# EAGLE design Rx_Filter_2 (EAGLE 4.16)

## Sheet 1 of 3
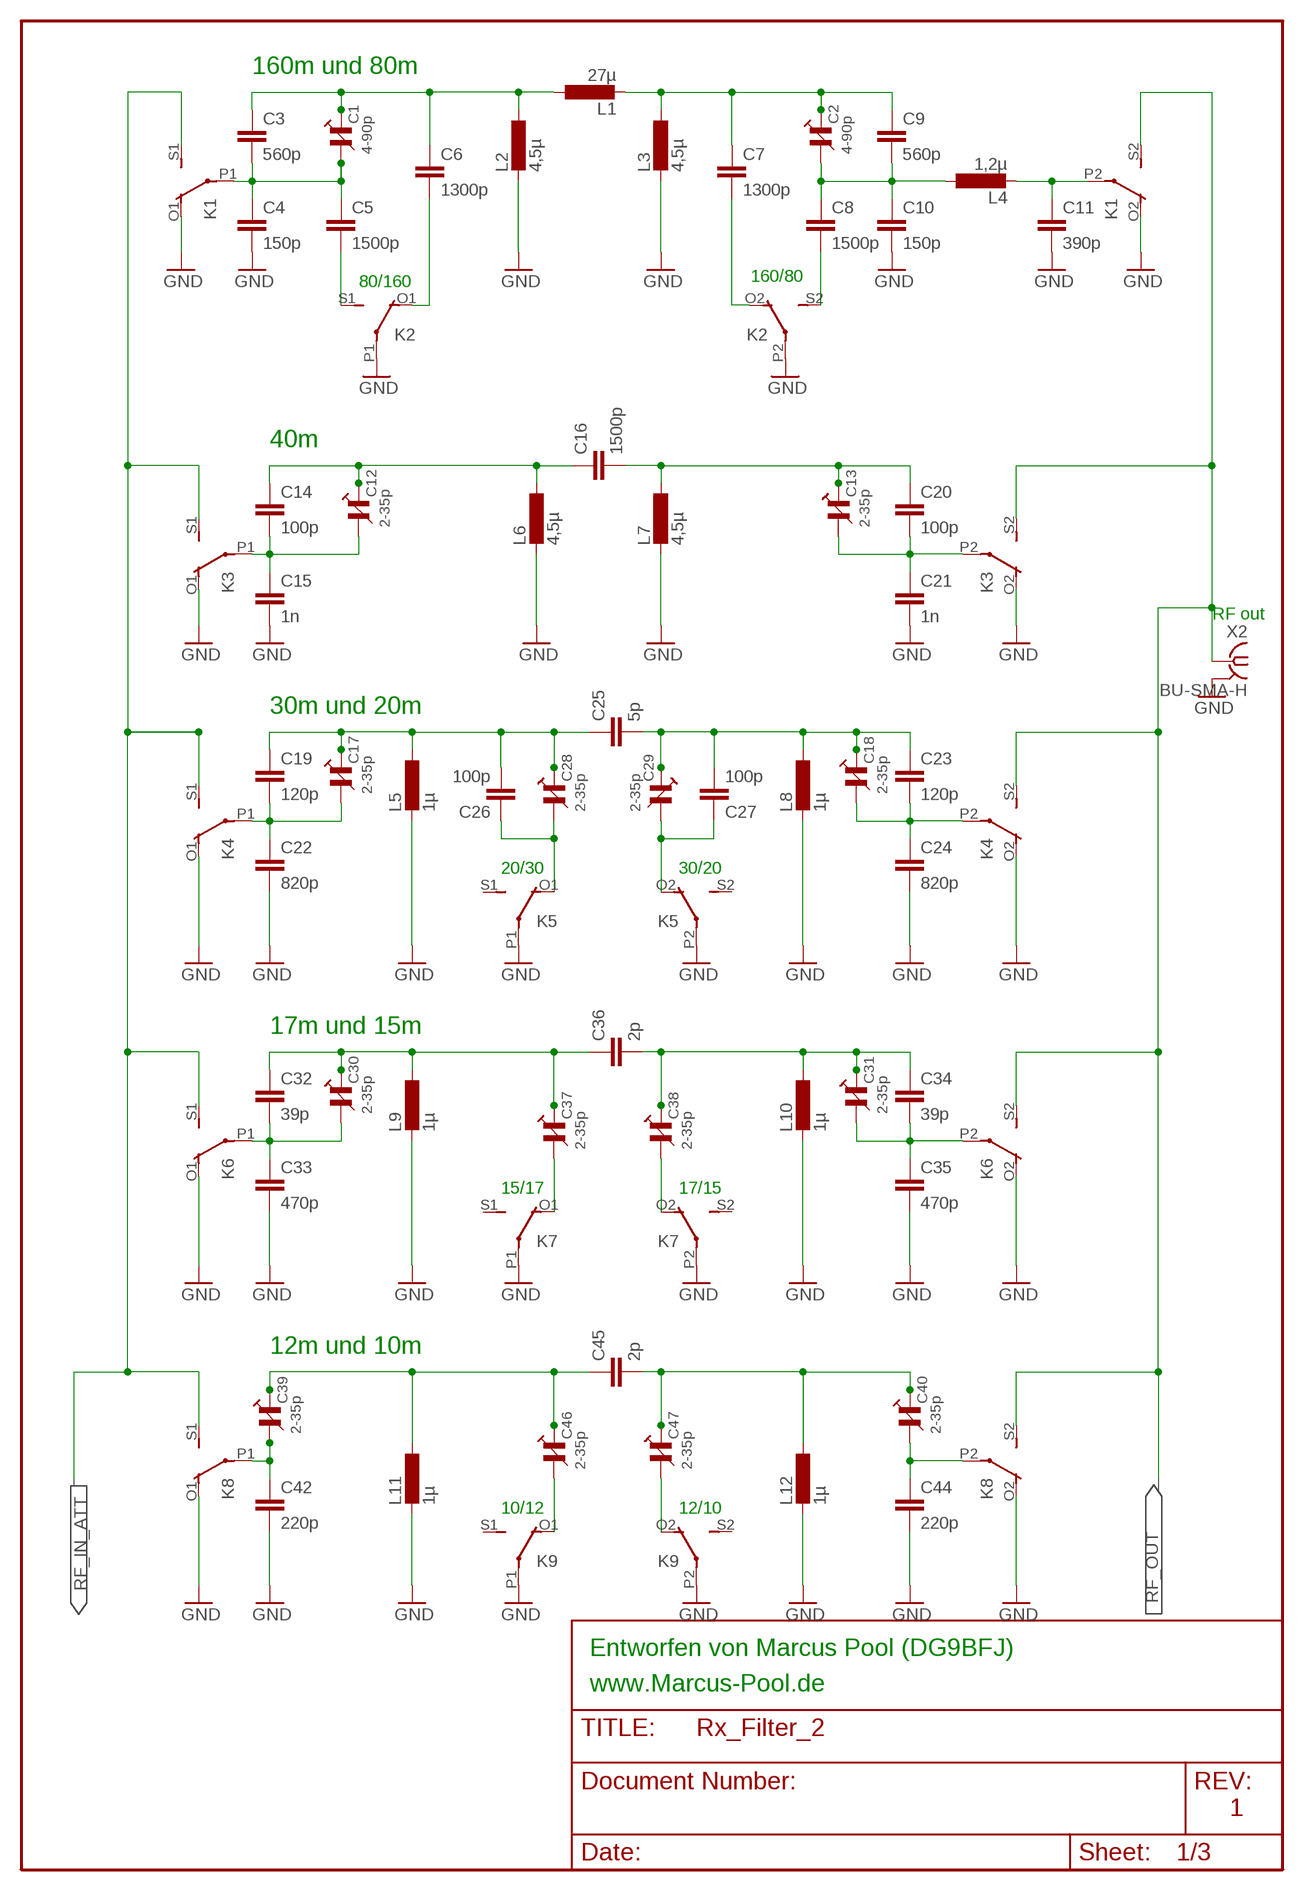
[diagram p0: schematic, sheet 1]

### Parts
C1  4-90p  808/3  [808/3]
C2  4-90p  808/3  [808/3]
C3  560p  C-EU050-050X075  [C050-050X075]
C4  150p  C-EU050-050X075  [C050-050X075]
C5  1500p  C-EU050-050X075  [C050-050X075]
C6  1300p  C-EU050-050X075  [C050-050X075]
C7  1300p  C-EU050-050X075  [C050-050X075]
C8  1500p  C-EU050-050X075  [C050-050X075]
C9  560p  C-EU050-050X075  [C050-050X075]
C10  150p  C-EU050-050X075  [C050-050X075]
C11  390p  C-EU050-050X075  [C050-050X075]
C12  2-35p  808/3  [808/3]
C13  2-35p  808/3  [808/3]
C14  100p  C-EU050-050X075  [C050-050X075]
C15  1n  C-EU050-050X075  [C050-050X075]
C16  1500p  C-EU050-050X075  [C050-050X075]
C17  2-35p  808/3  [808/3]
C18  2-35p  808/3  [808/3]
C19  120p  C-EU050-050X075  [C050-050X075]
C20  100p  C-EU050-050X075  [C050-050X075]
C21  1n  C-EU050-050X075  [C050-050X075]
C22  820p  C-EU050-050X075  [C050-050X075]
C23  120p  C-EU050-050X075  [C050-050X075]
C24  820p  C-EU050-050X075  [C050-050X075]
C25  5p  C-EU050-050X075  [C050-050X075]
C26  100p  C-EU050-050X075  [C050-050X075]
C27  100p  C-EU050-050X075  [C050-050X075]
C28  2-35p  808/3  [808/3]
C29  2-35p  808/3  [808/3]
C30  2-35p  808/3  [808/3]
C31  2-35p  808/3  [808/3]
C32  39p  C-EU050-050X075  [C050-050X075]
C33  470p  C-EU050-050X075  [C050-050X075]
C34  39p  C-EU050-050X075  [C050-050X075]
C35  470p  C-EU050-050X075  [C050-050X075]
C36  2p  C-EU050-050X075  [C050-050X075]
C37  2-35p  808/3  [808/3]
C38  2-35p  808/3  [808/3]
C39  2-35p  808/3  [808/3]
C40  2-35p  808/3  [808/3]
C42  220p  C-EU050-050X075  [C050-050X075]
C44  220p  C-EU050-050X075  [C050-050X075]
C45  2p  C-EU050-050X075  [C050-050X075]
C46  2-35p  808/3  [808/3]
C47  2-35p  808/3  [808/3]
K1  G6H2-100  [G6H2-100]
K2  G6H2-100  [G6H2-100]
K3  G6H2-100  [G6H2-100]
K4  G6H2-100  [G6H2-100]
K5  G6H2-100  [G6H2-100]
K6  G6H2-100  [G6H2-100]
K7  G6H2-100  [G6H2-100]
K8  G6H2-100  [G6H2-100]
K9  G6H2-100  [G6H2-100]
L1  27µ  L-EUTJ5-U1  [TJ5-U1]
L2  4,5µ  L-EUTJ3-U1  [TJ3-U1]
L3  4,5µ  L-EUTJ3-U1  [TJ3-U1]
L4  1,2µ  L-EUTJ3-U1  [TJ3-U1]
L5  1µ  L-EUTJ3-U1  [TJ3-U1]
L6  4,5µ  L-EUTJ3-U1  [TJ3-U1]
L7  4,5µ  L-EUTJ3-U1  [TJ3-U1]
L8  1µ  L-EUTJ3-U1  [TJ3-U1]
L9  1µ  L-EUTJ3-U1  [TJ3-U1]
L10  1µ  L-EUTJ3-U1  [TJ3-U1]
L11  1µ  L-EUTJ3-U1  [TJ3-U1]
L12  1µ  L-EUTJ3-U1  [TJ3-U1]
X2  BU-SMA-H  [BU-SMA-H]

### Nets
GND: C4.2 C10.2 C11.2 C15.2 C21.2 C22.2 C24.2 C33.2 C35.2 C42.2 C44.2 K1.O1(2:O) K1.O2(3:O) K2.P1(2:P) K2.P2(3:P) K3.O1(2:O) K3.O2(3:O) K4.O1(2:O) K4.O2(3:O) K5.P1(2:P) K5.P2(3:P) K6.O1(2:O) K6.O2(3:O) K7.P1(2:P) K7.P2(3:P) K8.O1(2:O) K8.O2(3:O) K9.P1(2:P) K9.P2(3:P) L2.2 L3.2 L5.2 L6.2 L7.2 L8.2 L9.2 L10.2 L11.2 L12.2 X2.2(GND) ; also sheet 2,3
N$1: C11.1 K1.P2(3:P) L4.2
N$2: C1.2 C3.2 C4.1 C5.1 K1.P1(2:P)
N$3: C1.1 C1.3 C3.1 C6.1 L1.1 L2.1
N$4: C2.1 C2.3 C7.1 C9.1 L1.2 L3.1
N$5: C2.2 C8.1 C9.2 C10.1 L4.1
N$6: C5.2 K2.S1(2:S)
N$7: C6.2 K2.O1(2:O)
N$8: C7.2 K2.O2(3:O)
N$9: C8.2 K2.S2(3:S)
N$12: C12.2 C14.2 C15.1 K3.P1(2:P)
N$13: C12.1 C12.3 C14.1 C16.1 L6.1
N$14: C13.1 C13.3 C16.2 C20.1 L7.1
N$15: C13.2 C20.2 C21.1 K3.P2(3:P)
N$16: C17.2 C19.2 C22.1 K4.P1(2:P)
N$17: C17.1 C17.3 C19.1 C25.1 C26.2 C28.1 C28.3 L5.1
N$18: C18.1 C18.3 C23.1 C25.2 C27.2 C29.1 C29.3 L8.1
N$19: C18.2 C23.2 C24.1 K4.P2(3:P)
N$20: C30.2 C32.2 C33.1 K6.P1(2:P)
N$21: C30.1 C30.3 C32.1 C36.1 C37.1 C37.3 L9.1
N$22: C26.1 C28.2 K5.O1(2:O)
N$23: C27.1 C29.2 K5.O2(3:O)
N$24: C31.1 C31.3 C34.1 C36.2 C38.1 C38.3 L10.1
N$25: C31.2 C34.2 C35.1 K6.P2(3:P)
N$26: C37.2 K7.O1(2:O)
N$27: C39.2 C42.1 K8.P1(2:P)
N$28: C39.1 C39.3 C45.1 C46.1 C46.3 L11.1
N$29: C40.1 C40.3 C45.2 C47.1 C47.3 L12.1
N$30: C38.2 K7.O2(3:O)
N$31: C40.2 C44.1 K8.P2(3:P)
N$32: C46.2 K9.O1(2:O)
N$33: C47.2 K9.O2(3:O)
RF_IN_ATT: K1.S1(2:S) K3.S1(2:S) K4.S1(2:S) K6.S1(2:S) K8.S1(2:S) ; also sheet 3
RF_OUT: K1.S2(3:S) K3.S2(3:S) K4.S2(3:S) K6.S2(3:S) K8.S2(3:S) X2.1 ; also sheet 3

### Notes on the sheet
- 160m und 80m
- 160/80
- 80/160
- 40m
- RF out
- 30m und 20m
- 20/30 | 30/20
- 17m und 15m
- 15/17 | 17/15
- 12m und 10m
- 10/12 | 12/10
- Entworfen von Marcus Pool (DG9BFJ)
- www.Marcus-Pool.de
- 1

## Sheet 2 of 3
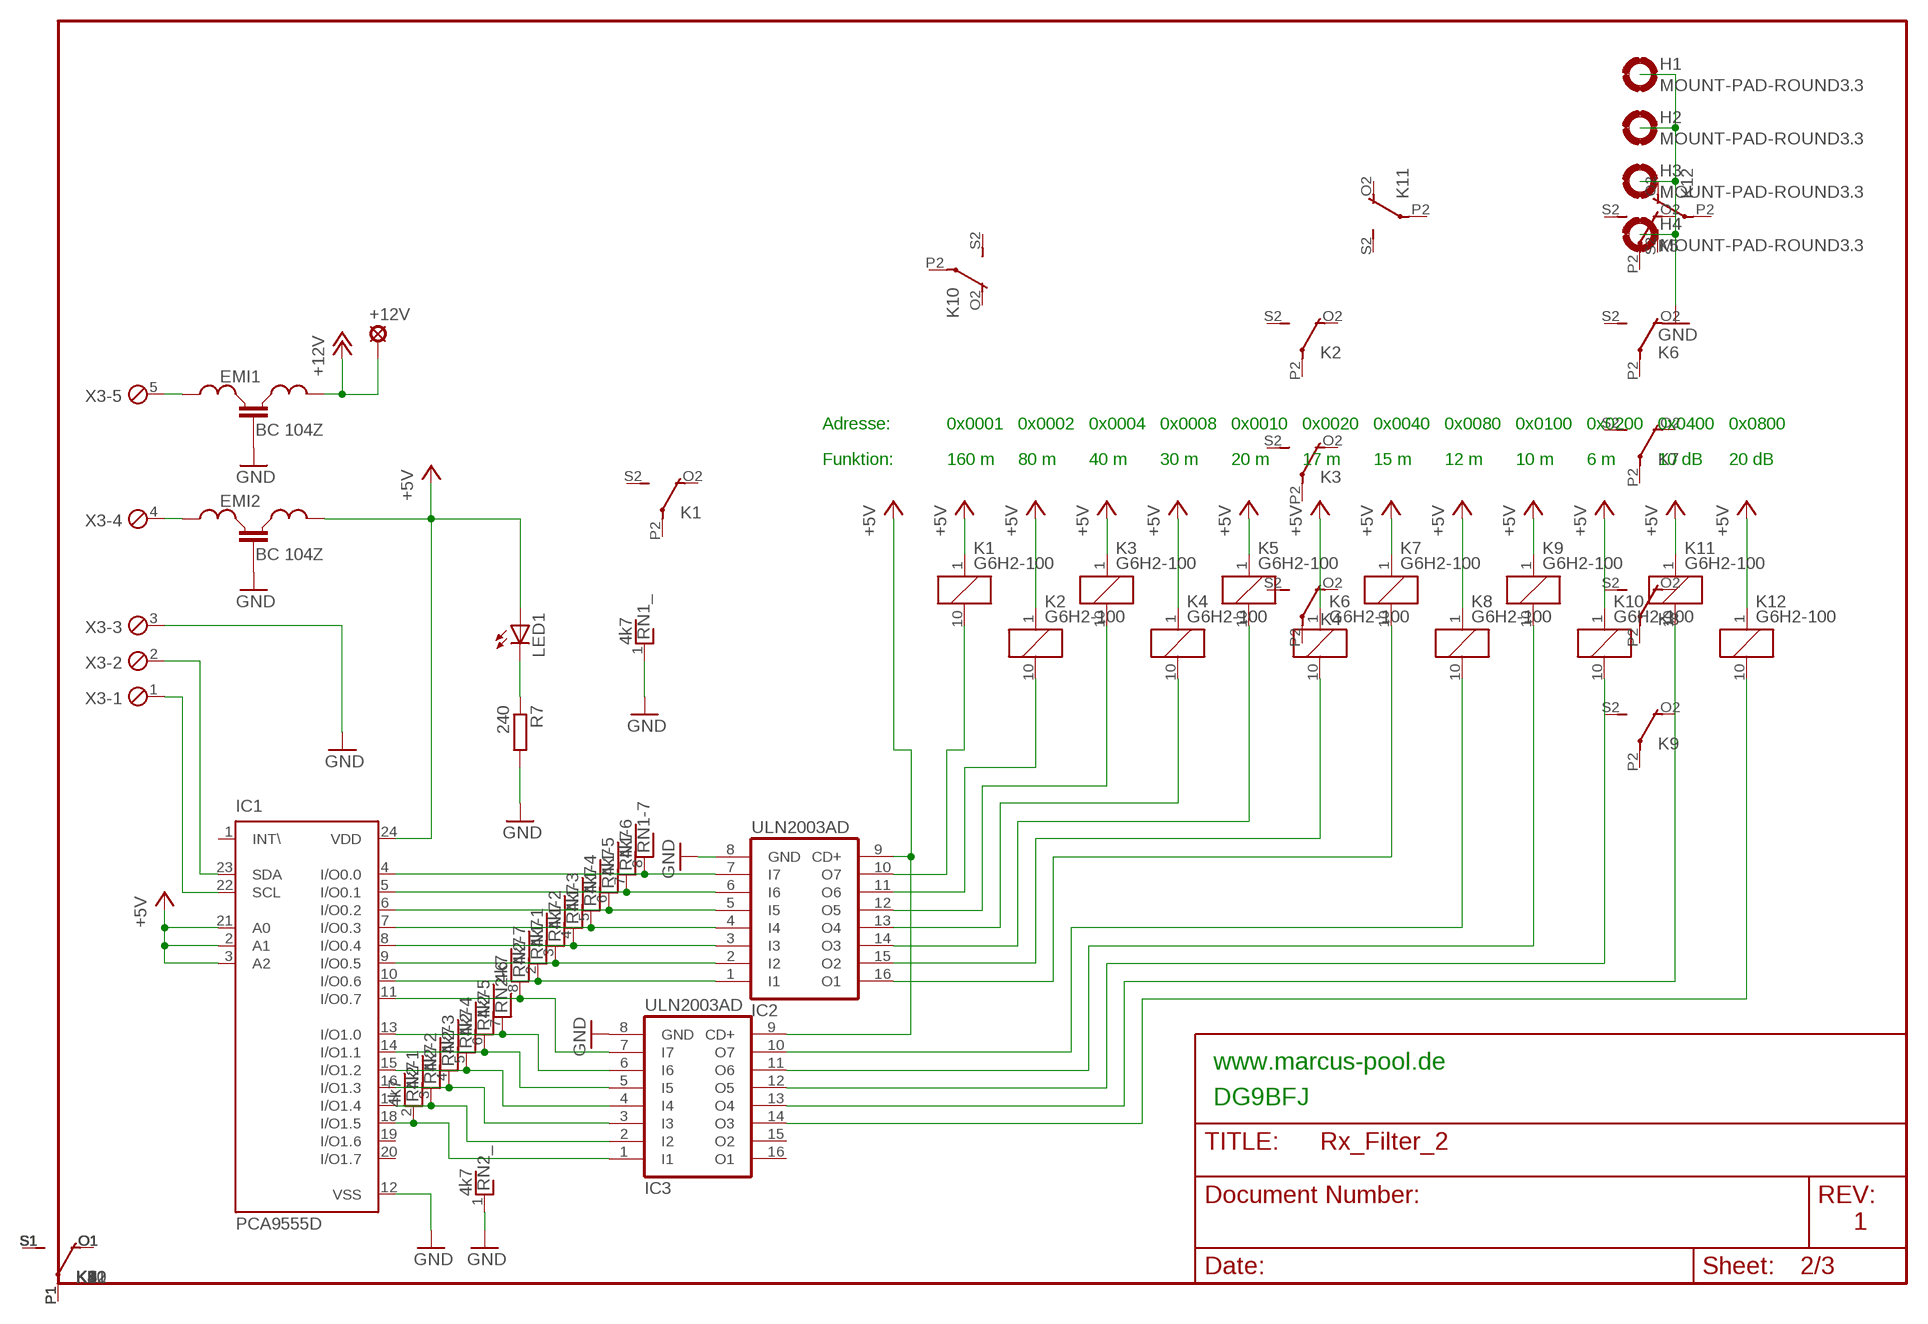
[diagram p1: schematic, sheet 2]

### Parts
+12V  LSP10  [LSP10]
EMI1  BC 104Z  DSS30655  [DSS30655]
EMI2  BC 104Z  DSS30655  [DSS30655]
H1  MOUNT-PAD-ROUND3.3  [3,3-PAD]
H2  MOUNT-PAD-ROUND3.3  [3,3-PAD]
H3  MOUNT-PAD-ROUND3.3  [3,3-PAD]
H4  MOUNT-PAD-ROUND3.3  [3,3-PAD]
IC1  PCA9555D  [SO24]
IC2  ULN2003AD  [SO16]
IC3  ULN2003AD  [SO16]
K10  G6H2-100  [G6H2-100]
K11  G6H2-100  [G6H2-100]
K12  G6H2-100  [G6H2-100]
LED1  LEDCHIP-LED0805  [CHIP-LED0805]
R7  240  R-EU_M0805  [M0805]
RN1  4k7  RNX7  [RN-8]
RN2  4k7  RNX7  [RN-8]
X3  MPT5  [5POL254]

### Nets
+5V: EMI2.3 IC1.2(A1) IC1.3(A2) IC1.21(A0) IC1.24(VDD) IC2.9(CD+) IC3.9(CD+) K1.1 K2.1 K3.1 K4.1 K5.1 K6.1 K7.1 K8.1 K9.1 K10.1 K11.1 K12.1 LED1.A
+12V: +12V.MP EMI1.3
GND: EMI1.2 EMI2.2 H1.B3,3(MOUNT) H2.B3,3(MOUNT) H3.B3,3(MOUNT) H4.B3,3(MOUNT) IC1.12(VSS) IC2.8(GND) IC3.8(GND) R7.2 RN1.1 RN2.1 X3.3 ; also sheet 1,3
N$10: IC1.10(I/O0.6) IC2.1(I1) RN1.2
N$34: IC1.9(I/O0.5) IC2.2(I2) RN1.3
N$39: IC1.8(I/O0.4) IC2.3(I3) RN1.4
N$40: IC1.7(I/O0.3) IC2.4(I4) RN1.5
N$41: IC1.6(I/O0.2) IC2.5(I5) RN1.6
N$42: IC1.5(I/O0.1) IC2.6(I6) RN1.7
N$43: IC1.4(I/O0.0) IC2.7(I7) RN1.8
N$44: IC1.11(I/O0.7) IC3.7(I7) RN2.8
N$45: IC1.13(I/O1.0) IC3.6(I6) RN2.7
N$46: IC1.14(I/O1.1) IC3.5(I5) RN2.6
N$47: IC1.15(I/O1.2) IC3.4(I4) RN2.5
N$48: IC1.16(I/O1.3) IC3.3(I3) RN2.4
N$49: IC1.17(I/O1.4) IC3.2(I2) RN2.3
N$50: IC1.18(I/O1.5) IC3.1(I1) RN2.2
N$51: IC2.10(O7) K1.10
N$54: IC2.11(O6) K2.10
N$55: IC2.12(O5) K3.10
N$56: IC2.13(O4) K4.10
N$57: IC2.14(O3) K5.10
N$58: IC2.15(O2) K6.10
N$59: IC2.16(O1) K7.10
N$60: IC3.10(O7) K8.10
N$61: IC3.11(O6) K9.10
N$62: IC3.12(O5) K10.10
N$68: IC3.13(O4) K11.10
N$69: IC3.14(O3) K12.10
N$70: IC1.22(SCL) X3.1
N$71: IC1.23(SDA) X3.2
N$72: LED1.C R7.1
N$73: EMI1.1 X3.5
N$74: EMI2.1 X3.4
Unconnected: IC1.1(INT\) IC1.19(I/O1.6) IC1.20(I/O1.7) IC3.15(O2) IC3.16(O1) K5.S1(2:S) K5.S2(3:S) K7.S1(2:S) K7.S2(3:S) K9.S1(2:S) K9.S2(3:S)

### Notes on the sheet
- Adresse: | 0x0001 | 0x0002 | 0x0004 | 0x0008 | 0x0010 | 0x0020 | 0x0040 | 0x0080 | 0x0100 | 0x0200 | 0x0400 | 0x0800
- Funktion: | 160 m | 80 m | 40 m | 30 m | 20 m | 17 m | 15 m | 12 m | 10 m | 6 m | 10 dB | 20 dB
- www.marcus-pool.de
- DG9BFJ
- 1

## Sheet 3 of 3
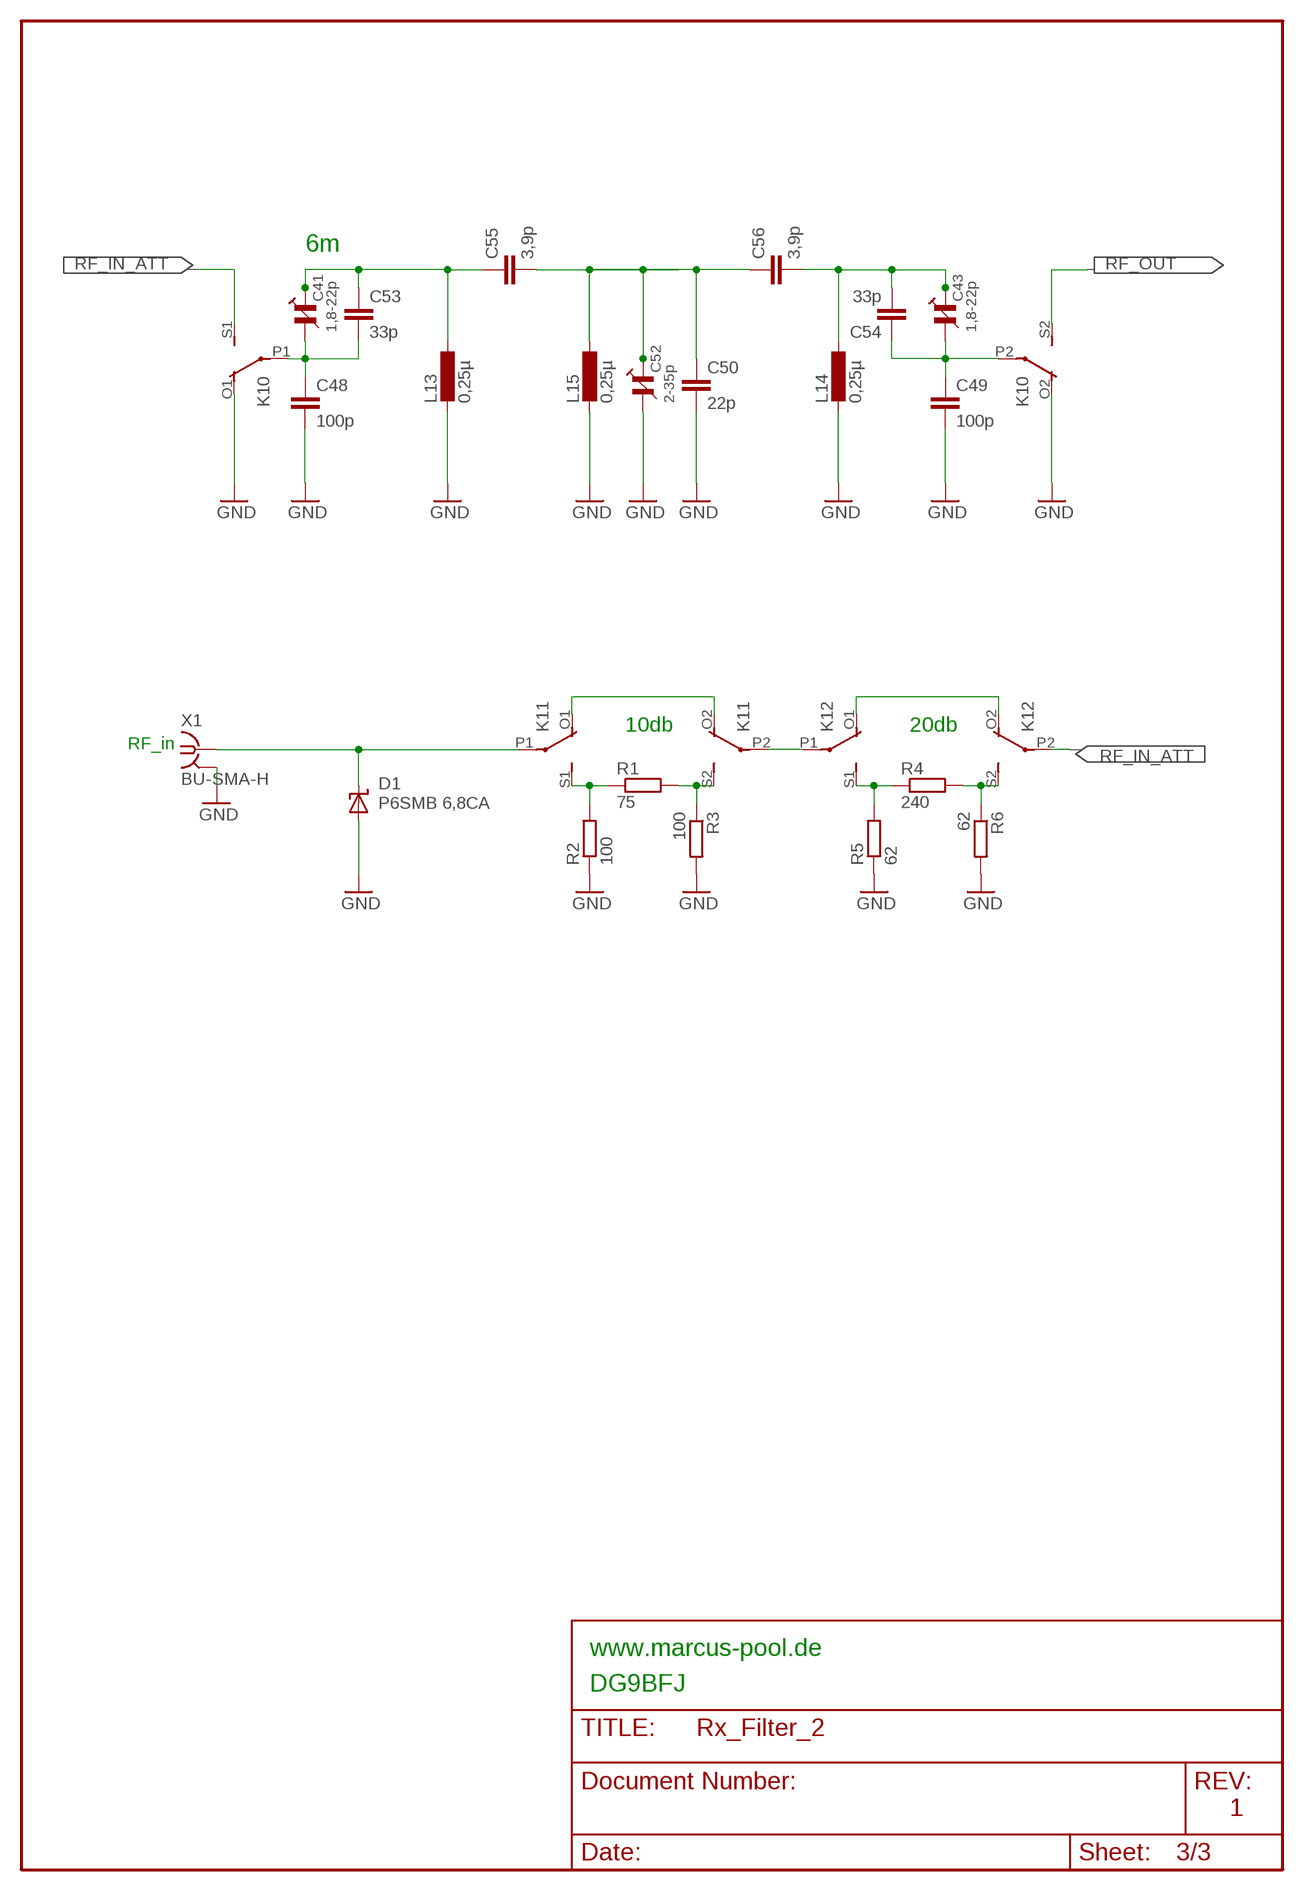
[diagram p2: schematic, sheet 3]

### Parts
C41  1,8-22p  808/3  [808/3]
C43  1,8-22p  808/3  [808/3]
C48  100p  C-EU050-050X075  [C050-050X075]
C49  100p  C-EU050-050X075  [C050-050X075]
C50  22p  C-EU050-050X075  [C050-050X075]
C52  2-35p  808/3  [808/3]
C53  33p  C-EU050-050X075  [C050-050X075]
C54  33p  C-EU050-050X075  [C050-050X075]
C55  3,9p  C-EU050-050X075  [C050-050X075]
C56  3,9p  C-EU050-050X075  [C050-050X075]
D1  P6SMB 6,8CA  SUPPRESSOR-SMBJ  [SMBJ]
L13  0,25µ  L-EUTJ3-U1  [TJ3-U1]
L14  0,25µ  L-EUTJ3-U1  [TJ3-U1]
L15  0,25µ  L-EUTJ3-U1  [TJ3-U1]
R1  75  R-EU_M0805  [M0805]
R2  100  R-EU_M0805  [M0805]
R3  100  R-EU_M0805  [M0805]
R4  240  R-EU_M0805  [M0805]
R5  62  R-EU_M0805  [M0805]
R6  62  R-EU_M0805  [M0805]
X1  BU-SMA-H  [BU-SMA-H]

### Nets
GND: C48.2 C49.2 C50.2 C52.2 D1.A K10.O1(2:O) K10.O2(3:O) L13.2 L14.2 L15.2 R2.1 R3.2 R5.1 R6.2 X1.2(GND) ; also sheet 1,2
N$11: C41.2 C48.1 C53.2 K10.P1(2:P)
N$35: C41.1 C41.3 C53.1 C55.1 L13.1
N$36: C43.1 C43.3 C54.2 C56.2 L14.1
N$37: C43.2 C49.1 C54.1 K10.P2(3:P)
N$38: C50.1 C52.1 C52.3 C55.2 C56.1 L15.1
N$52: K11.O1(2:O) K11.O2(3:O)
N$53: K11.S1(2:S) R1.1 R2.2
N$63: K11.S2(3:S) R1.2 R3.1
N$64: K11.P2(3:P) K12.P1(2:P)
N$65: K12.O1(2:O) K12.O2(3:O)
N$66: K12.S1(2:S) R4.1 R5.2
N$67: K12.S2(3:S) R4.2 R6.1
N$76: D1.C K11.P1(2:P) X1.1
RF_IN_ATT: K10.S1(2:S) K12.P2(3:P) ; also sheet 1
RF_OUT: K10.S2(3:S) ; also sheet 1

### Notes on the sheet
- 6m
- 10db | 20db
- RF_in
- www.marcus-pool.de
- DG9BFJ
- 1

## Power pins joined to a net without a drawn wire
GND: X1.3(GND) X1.4(GND) X1.5(GND) X2.3(GND) X2.4(GND) X2.5(GND)

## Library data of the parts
+12V = solpad:LSP10: SOLDER PAD
C1 C2 C12 C13 C17 C18 C28-C31 C37-C41 C43 C46 C47 C52 = Cap-Dreh:808/3
C3-C11 C14-C16 C19-C27 C32-C36 C42 C44 C45 C48-C50 C53-C56 = rcl:C-EU: CAPACITOR, European symbol
D1 = diode:SUPPRESSOR-: Suppressor diode
EMI1 EMI2 = ds(s)30655:DSS30655
H1-H4 = holes:MOUNT-PAD-ROUND: MOUNTING PAD, round
IC1 = micro-philips:PCA9555: 16-bit I2C and SMBus I/O port with interrupt Source: PCA9555_5.pdf
IC2 IC3 = uln-udn:ULN2003A: DRIVER ARRAY
K1-K12 = relay:G6H2-100: RELAY 2 x switch, 0.5 A/125 V AC, 1 A/30 V DC, Omron
L1-L15 = rcl:L-EU: INDUCTOR, European symbol
LED1 = led:LED: LED
R1-R7 = rcl:R-EU_: RESISTOR, European symbol
RN1 RN2 = resistor-net:RNX7: RESISTOR NETWORK
X1 X2 = RSC_IB_LIB:BU-SMA-H
X3 = con-phoenix-254:MPT5: PHOENIX CONNECTOR

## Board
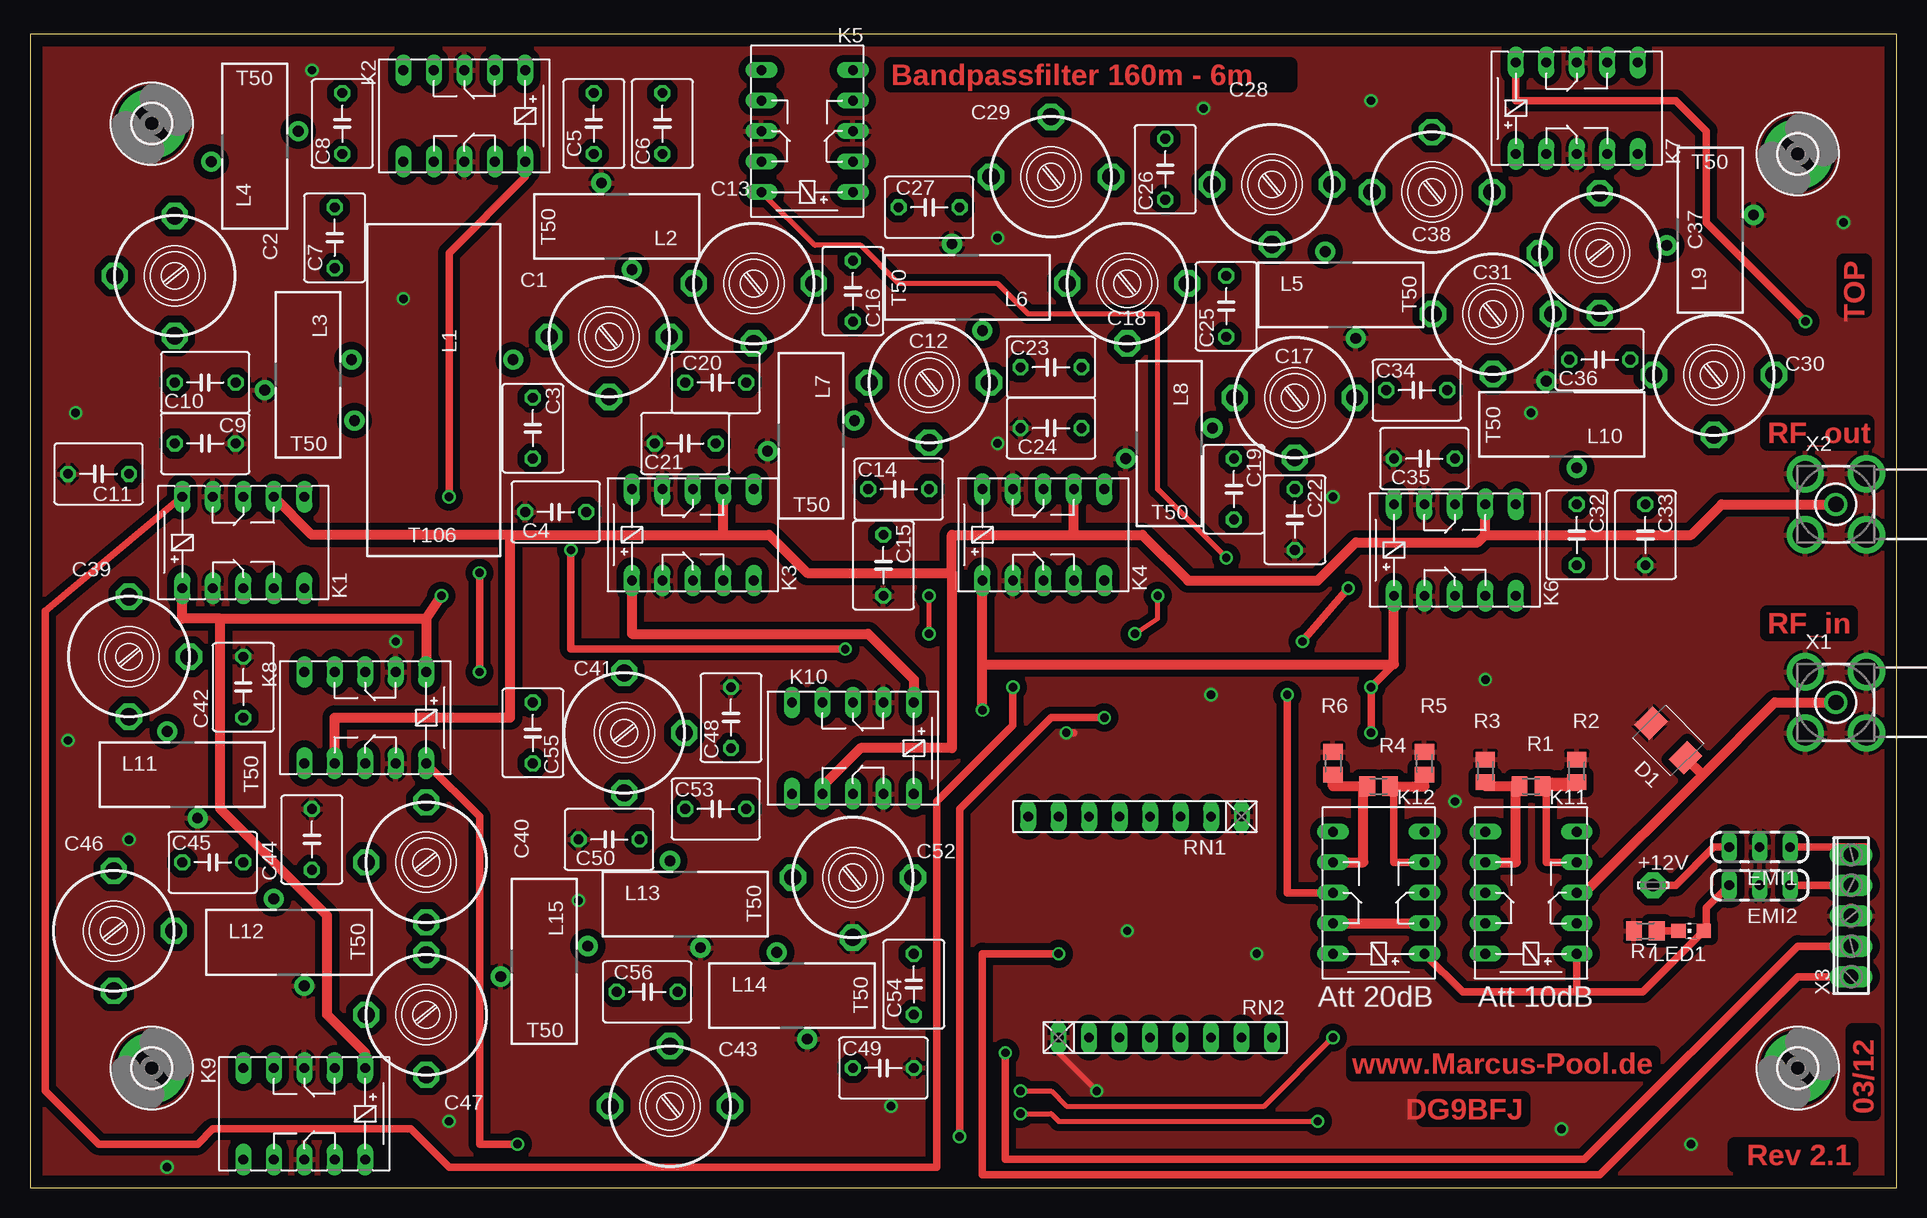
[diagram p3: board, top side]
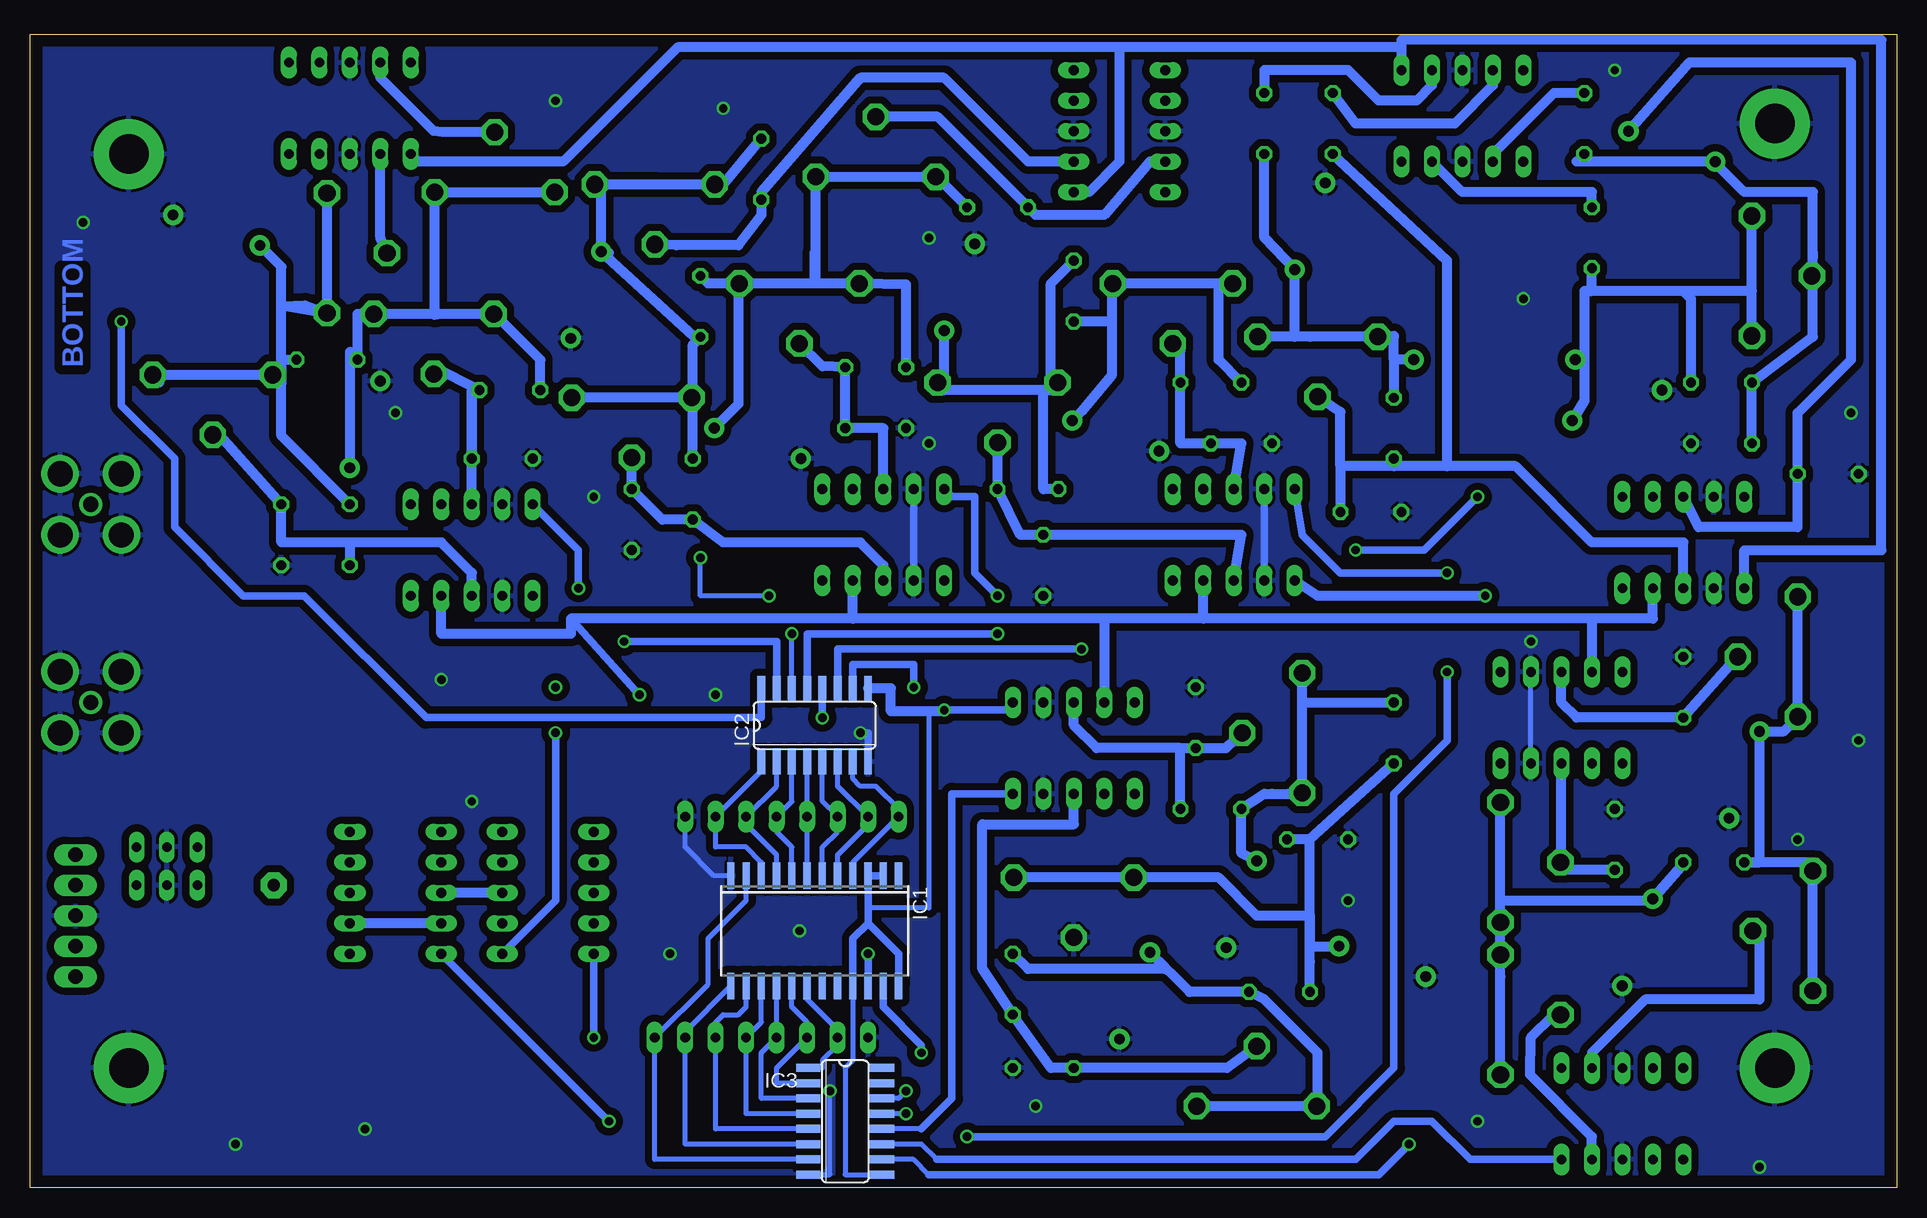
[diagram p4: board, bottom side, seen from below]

Size 155.56 x 96.19 mm. Coordinates in mm from the lower left corner, seen from the top.
Outline: 0,0 155.56,0 155.56,96.19 0,96.19 0,0
Copper layers (1*16): Top 0.035mm / dielectric 1.5mm / Bottom 0.035mm
Design rules "Bilex DRU": minimum track width 10mil, minimum drill 24mil, track to track 10mil, track to pad 10mil, pad to pad 10mil, via to via 10mil, smd to smd 10mil, copper to edge 40mil, drill to drill 8mil, minimum pad ring 10mil, minimum via ring 8mil, stop-mask expansion 4mil, vias tented up to drill 0mil, thermal gap 10mil

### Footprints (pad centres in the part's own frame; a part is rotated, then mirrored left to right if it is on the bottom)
LSP10 = drill 1.016 pad 2.159 octagon: MP 0,0
808/3 = drill 1.422 pad 2.184 octagon: 1 -5,0; 2 0,-5; 3 5,0
C050-050X075 = drill 0.813 octagon: 1 -2.54,0; 2 2.54,0
SMBJ = smd 1.78 x 2.16: A 2.04,0; C -2.03,0
DSS30655 = drill 0.8 long: 1 -2.54,0; 2 0,0; 3 2.54,0
3,3-PAD = drill 3.3 pad 5.842 round: B3,3 0,0
SO24 = smd 0.6 x 2.2: 1 -6.985,-4.6; 2 -5.715,-4.6; 3 -4.445,-4.6; 4 -3.175,-4.6; 5 -1.905,-4.6; 6 -0.635,-4.6; 7 0.635,-4.6; 8 1.905,-4.6; 9 3.175,-4.6; 10 4.445,-4.6; 11 5.715,-4.6; 12 6.985,-4.6; 13 6.985,4.6; 14 5.715,4.6; 15 4.445,4.6; 16 3.175,4.6; 17 1.905,4.6; 18 0.635,4.6; 19 -0.635,4.6; 20 -1.905,4.6; 21 -3.175,4.6; 22 -4.445,4.6; 23 -5.715,4.6; 24 -6.985,4.6
SO16 = smd 0.66 x 2.032: 1 -4.445,-3.073; 2 -3.175,-3.073; 3 -1.905,-3.073; 4 -0.635,-3.073; 5 0.635,-3.073; 6 1.905,-3.073; 7 3.175,-3.073; 8 4.445,-3.073; 9 4.445,3.073; 10 3.175,3.073; 11 1.905,3.073; 12 0.635,3.073; 13 -0.635,3.073; 14 -1.905,3.073; 15 -3.175,3.073; 16 -4.445,3.073
G6H2-100 = drill 0.813 long: 1 -5.08,-3.81; 5 5.08,-3.81; 6 5.08,3.81; 10 -5.08,3.81; O1 -2.54,-3.81; O2 -2.54,3.81; P1 0,-3.81; P2 0,3.81; S1 2.54,-3.81; S2 2.54,3.81
TJ5-U1 = drill 0.9 pad 1.676 round: 1 -6.605,-2.54; 2 6.605,2.54
TJ3-U1 = drill 0.9 pad 1.676 round: 1 -3.935,-1.27; 2 3.3,1.27
CHIP-LED0805 = smd 1.2 x 1.2: A 0,-1.05; C 0,1.05
M0805 = smd 1.3 x 1.6: 1 -0.95,0; 2 0.95,0
RN-8 = drill 0.813 long: 1 -8.89,0; 2 -6.35,0; 3 -3.81,0; 4 -1.27,0; 5 1.27,0; 6 3.81,0; 7 6.35,0; 8 8.89,0
BU-SMA-H = drill 1.27 round: 1 0,0 | drill 2.1 round: 2 -2.55,2.55; 3 2.55,2.55; 4 2.55,-2.55; 5 -2.55,-2.55
5POL254 = drill 1.2 long: 1 -5.08,0; 2 -2.54,0; 3 0,0; 4 2.54,0; 5 5.08,0

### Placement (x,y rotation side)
+12V  135.25,25.23 0 top
C1  48.25,70.95 0 top
C2  12.06,76.03 270 top
C3  41.9,63.34 270 top
C4  43.81,56.35 180 top
C5  46.98,88.73 90 top
C6  52.7,88.73 90 top
C7  25.39,79.21 90 top
C8  26.03,88.73 90 top
C9  14.6,67.14 180 top
C10  14.6,62.06 0 top
C11  5.71,59.52 180 top
C12  74.93,67.14 0 top
C13  60.32,75.4 0 top
C14  72.39,58.26 0 top
C15  71.12,51.91 270 top
C16  68.58,74.77 270 top
C17  105.41,65.88 0 top
C18  91.44,75.4 0 top
C19  100.33,58.26 270 top
C20  57.14,67.14 0 top
C21  54.6,62.06 180 top
C22  105.41,55.72 270 top
C23  85.09,68.41 0 top
C24  85.09,63.34 180 top
C25  99.69,73.49 90 top
C26  94.61,84.92 90 top
C27  74.93,81.75 0 top
C28  103.5,83.65 0 top
C29  85.09,84.29 180 top
C30  140.33,67.78 0 top
C31  121.92,72.86 0 top
C32  128.9,54.45 270 top
C33  134.62,54.45 270 top
C34  115.56,66.51 0 top
C35  116.2,60.8 180 top
C36  130.81,69.05 180 top
C37  130.81,77.94 270 top
C38  116.84,83.02 180 top
C39  8.25,44.29 90 top
C40  33.02,27.14 270 top
C41  49.52,37.94 90 top
C42  17.78,41.74 90 top
C43  53.34,6.82 180 top
C44  23.49,29.05 90 top
C45  15.23,27.14 0 top
C46  6.98,21.43 90 top
C47  33.02,14.44 270 top
C48  58.41,39.2 90 top
C49  71.12,10 0 top
C50  48.25,29.05 180 top
C52  68.58,25.87 0 top
C53  57.14,31.59 0 top
C54  73.66,16.98 90 top
C55  41.9,37.94 270 top
C56  51.43,16.35 0 top
D1  136.52,37.3 135 top
EMI1  144.14,28.41 180 top
EMI2  144.14,25.23 180 top
H1  147.31,10 0 top
H2  147.31,86.19 0 top
H3  10.15,10 0 top
H4  10.15,88.73 0 top
IC1  90.17,21.43 180 bottom
IC2  90.17,38.57 0 bottom
IC3  87.62,5.55 270 bottom
K1  17.78,53.81 0 top
K2  36.19,89.37 180 top
K3  55.24,54.45 0 top
K4  84.45,54.45 0 top
K5  64.77,88.1 90 top
K6  118.74,53.18 0 top
K7  128.9,90 0 top
K8  27.94,39.2 180 top
K9  22.86,6.18 180 top
K10  68.58,36.66 180 top
K11  125.09,24.6 90 top
K12  112.39,24.6 90 top
L1  33.65,66.51 180 top
L2  48.89,80.48 90 top
L3  22.86,67.78 180 top
L4  19.05,86.83 0 top
L5  109.22,74.13 270 top
L6  78.1,75.4 90 top
L7  64.77,62.7 180 top
L8  94.61,62.06 180 top
L9  140.33,79.84 0 top
L10  127.63,63.97 90 top
L11  12.69,34.12 270 top
L12  21.59,20.16 270 top
L13  54.6,23.33 270 top
L14  63.49,15.71 270 top
L15  42.54,18.89 180 top
LED1  138.43,21.43 90 top
R1  125.09,33.49 180 top
R2  128.9,34.76 270 top
R3  121.28,34.76 90 top
R4  112.39,33.49 180 top
R5  116.2,35.4 270 top
R6  108.58,35.4 90 top
R7  134.62,21.43 180 top
RN1  92.07,30.95 180 top
RN2  94.61,12.54 0 top
X1  150.49,40.48 0 top
X2  150.49,56.98 0 top
X3  151.76,22.7 90 top

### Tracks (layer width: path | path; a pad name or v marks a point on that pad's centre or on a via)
+5V  (via drill 0.7, 0.7 pad 1.02)
  Top 0.61: K12.1 119.38,16.35 128.9,16.35 | 128.9,16.35 K11.1 | v111.76,37.94 v111.76,41.74 113.66,43.65 | 128.9,16.35 134.4,16.35 LED1.A 139.69,21.43 139.69,23.33 EMI2.3
  Top 0.813: 33.02,47.46 K8.1 | 33.02,47.46 v34.28,49.37 | 15.87,47.46 33.02,47.46 | K3.1 50.16,46.19 69.84,46.19 73.66,42.38 K10.1 | 79.37,43.65 K4.1 | K6.1 113.66,43.65 79.37,43.65 | v79.37,39.84 79.37,43.65 | K9.1 27.94,11.27 24.76,14.44 24.76,22.7 15.87,31.59 15.87,47.46 | 15.87,47.46 12.69,47.46 K1.1
  Bottom 0.406: IC1.3 85.72,25.87 85.56,26.03 | IC3.9 87.62,1.1 87.62,10 86.99,10.63 86.99,16.98 IC1.21 | 83.81,39.74 80.64,39.74 80.64,23.33 85.72,23.33
  Bottom 0.61: K10.1 73.66,39.84 v79.37,39.84 | K12.1 111.76,23.96 v111.76,37.94 | 86.99,16.98 86.99,20.79 85.72,22.06 | 85.72,22.06 85.72,23.33 85.72,25.87 | IC1.24 83.18,19.52 85.72,22.06 | 85.56,26.03 IC1.2
  Bottom 0.813: 41.27,95.08 64.77,95.08 | 64.77,95.08 64.77,85.56 67.31,83.02 K5.1 | K7.1 123.19,85.56 111.12,85.56 101.59,95.08 64.77,95.08 | K3.1 48.25,49.37 v34.28,49.37 | v79.37,39.84 79.37,39.74 83.81,39.74 83.81,41.64 IC2.9 | 41.27,95.08 41.27,95.72 1.27,95.72 1.27,53.18 12.69,53.18 K1.1 | 41.27,95.08 K2.1
+12V
  Top 0.61: EMI1.3 140.33,28.41 137.16,25.23 +12V.MP
GND  (via drill 0.7, 0.7 pad 1.02)
  Top 0.406: v88.9,8.09 85.72,11.27 RN2.1
  Top 0.61: v86.36,37.94 86.99,37.94
  Bottom 0.406: IC1.12 98.58,26.03 100.96,28.41 RN1.1 | IC3.8 88.9,1.1 v88.9,8.09 | K8.O2 K8.O1
  Bottom 0.61: IC2.8 85.72,37.94 v86.36,37.94 | K3.O1 K3.O2 | K4.O1 K4.O2
  other vias: 118.74,32.22 97.79,90 111.76,90.64 151.12,80.48 121.28,42.38 125.09,64.6 80.64,79.21 80.64,62.06 31.11,74.13 3.17,37.3 8.25,29.05 34.92,5.55 45.71,23.96 71.75,6.82 30.48,45.55 127.63,4.92 138.43,3.65 102.23,19.52 23.49,93.18 3.81,64.6 91.44,21.43 108.58,57.62 98.42,41.11 11.42,1.74
  pour Top (isolate 0.61): 0.63,95.72 154.94,95.72 154.94,0.47 0.63,0.47
  pour Bottom (isolate 0.61): 0.63,95.72 154.94,95.72 154.94,0.47 0.63,0.47
N$1
  Bottom 0.813: K1.P2 16.51,55.08 8.25,55.08 C11.1 8.25,64.6 3.81,69.05 3.81,93.81 17.27,93.81 L4.2
N$2
  Bottom 0.813: C1.2 46.35,64.68 46.35,60.16 | 46.35,60.16 C4.1 | 41.9,60.16 46.35,60.16 | C5.1 37.46,77.3 37.46,60.16 | 37.46,60.16 31.75,60.16 25.39,53.81 17.78,53.81 K1.P1 | 37.46,60.16 41.9,60.16 | 41.9,60.16 C3.2
N$3
  Bottom 0.813: 41.9,69.05 C3.1 | 41.9,70.95 C1.1 | C1.1 48.89,70.95 | 48.89,70.95 50.16,70.95 L2.1 52.7,79.21 C6.1 | C1.1 41.9,71.03 41.9,70.95 | L1.1 41.9,69.05 | 41.9,69.05 41.9,70.95 | 48.89,70.95 C1.3
N$4
  Bottom 0.813: 26.67,69.05 L3.1 26.03,69.05 | 26.03,74.77 26.03,69.05 | 26.03,74.77 25.39,74.77 C7.1 | 26.03,69.05 26.03,65.62 L1.2 | 17.78,74.77 26.03,74.77 | 12.06,74.77 17.78,74.77 | 17.78,74.77 17.14,74.13 C9.1 | C2.3 12.06,74.77 | 12.06,74.77 C2.1
N$5
  Bottom 0.813: C10.1 C9.2 6.98,70.95 6.98,77.94 | 6.98,77.94 6.98,83.02 12.69,83.02 15.23,85.56 | 6.98,77.94 C2.2 | 15.23,85.56 L4.1 | 15.23,85.56 26.67,85.56 C8.1
N$6
  Bottom 0.813: K2.S1 33.65,91.91 36.82,88.73 45.08,88.73 C5.2
N$7
  Bottom 0.813: K2.O1 38.73,91.91 40,90.64 43.17,90.64 45.71,93.18 52.7,93.18 C6.2
N$8
  Bottom 0.813: K2.O2 36.19,83.02 25.39,83.02 C7.2
N$9
  Bottom 0.813: K2.S2 33.65,86.19 28.57,91.27 C8.2
N$10
  Bottom 0.406: IC2.1 94.61,34.76 RN1.2 98.42,28.41 95.88,28.41 94.61,27.14 IC1.10
N$11
  Bottom 0.813: K10.P1 68.58,38.57 66.67,36.66 59.68,36.66 | 59.68,36.66 C48.1 55.88,36.66 | 55.88,36.66 C41.2 | 59.68,36.66 55.88,36.66 | C53.2 59.68,36.66
N$12
  Bottom 0.813: K3.P1 54.6,54.45 C15.1 73.02,54.45 C14.2 C12.2
N$13
  Bottom 0.813: C14.1 71.12,58.26 71.12,66.51 | 71.12,66.51 C12.1 70.48,66.51 | 71.12,66.51 70.48,66.51 | 79.37,66.51 L6.1 | 70.48,66.51 70.48,75.4 C16.1 | 71.12,66.51 79.37,66.51 | 79.37,66.51 C12.3
N$14
  Bottom 0.813: L7.1 67.94,64.73 65.4,67.78 65.4,74.13 | 65.4,74.13 65.4,72.22 C16.2 | 65.4,74.13 65.4,75.4 C13.3 C13.1 | C13.1 55.24,75.4 | C13.1 55.24,75.32 56.51,75.4 56.51,69.05 C20.1
N$15
  Bottom 0.813: C13.2 59.68,69.77 C20.2 59.68,62.06 C21.1 54.6,62.06 K3.P2
N$16
  Bottom 0.813: C17.2 C22.1 102.87,55.72 C19.2 97.79,53.81 86.36,53.81 84.45,51.91 K4.P1
N$17
  Bottom 0.813: C19.1 100.33,65.79 C17.1 100.33,65.88 | 100.33,65.88 100.33,70.32 C25.1 100.2,70.95 L5.1 | L5.1 107.31,77.94 | 107.95,83.73 C28.1 | L5.1 107.95,83.73 | 107.95,83.73 107.39,83.65 C28.3 C28.1 | C28.1 97.79,83.65 C26.2 | 100.33,65.88 C17.3
N$18
  Bottom 0.813: C25.2 99.06,75.4 96.52,75.4 | C18.1 86.36,75.4 | C18.1 90.17,75.4 | C18.1 C18.3 | C18.3 96.52,75.4 | L8.1 96.52,65.36 96.52,75.4 | C18.1 82.55,75.32 C23.1 | 90.09,77.94 90.09,75.48 90.17,75.4 | 90.09,77.94 C29.1 C29.3 80.01,84.29 C27.2 | 90.09,77.94 90.17,77.94 90.17,75.4 | 90.17,75.4 C18.3
N$19
  Bottom 0.813: C18.2 89.53,68.49 C23.2 C24.1 84.45,63.34 K4.P2
N$20
  Bottom 0.813: K6.P1 118.74,51.27 121.28,53.81 128.9,53.81 | 128.9,53.81 134.62,53.81 C33.1 139.78,62.78 C30.2 | 128.9,53.81 C32.2
N$21
  Bottom 0.813: C30.1 134.62,68.41 | C30.1 134.62,67.06 134.62,62.7 C32.1 | C30.1 134.62,67.14 134.62,68.41 | 134.62,73.49 134.62,73.57 | L9.1 134.62,76.79 134.62,73.57 | 134.62,68.41 134.62,69.05 | 134.62,69.05 134.62,73.49 | 134.62,69.05 C36.1 | C37.3 132.63,73.57 134.62,73.49 | C37.3 C37.1 | 134.62,73.57 C37.3 | 144.78,67.14 C30.3 C30.1
N$22
  Bottom 0.813: C28.2 101.68,78.57 96.52,78.57 94.61,81.11 C26.1 94.61,83.02 86.36,92.54 79.37,92.54 72.39,85.56 K5.O1
N$23
  Bottom 0.813: C29.2 79.93,89.29 C27.1 71.75,81.11 66.04,81.11 62.22,85.56 K5.O2
N$24
  Bottom 0.813: 121.28,72.86 C31.3 128.27,72.86 C36.2 128.9,69.68 L10.1 | 116.84,72.86 C31.1 | C31.1 121.28,72.86 | 117.47,72.86 121.28,72.86 | C31.1 117.47,72.86 | 116.84,72.86 117.47,72.86 | 116.84,72.86 113.03,69.05 C34.1 | 111.76,83.02 C38.3 C38.1 121.84,72.78 121.28,72.86
N$25
  Bottom 0.813: 118.74,66.51 C34.2 121.92,68.41 C31.2 | K6.P2 118.74,66.51 | 118.74,66.51 C35.1
N$26
  Bottom 0.813: C37.2 126.36,79.21 K7.O1
N$27
  Bottom 0.813: C39.2 C42.1 26.67,39.2 27.94,40.48 K8.P1
N$28
  Bottom 0.813: C39.3 C39.1 8.25,39.2 9.39,38.06 L11.1 11.42,27.14 C45.1 6.98,27.14 6.98,26.59 6.26,26.59 C46.3 C46.1
N$29
  Bottom 0.813: C45.2 17.65,27.14 L12.1 20.32,23.96 33.02,23.96 | 33.02,32.22 C40.1 33.02,23.96 | C40.3 C47.1 33.02,17.62 | 33.02,9.36 C47.3 33.02,17.62 | 33.02,17.62 C40.3 | C40.3 33.02,23.96
N$30
  Bottom 0.813: C38.2 121.2,88.02 121.92,88.1 126.36,92.54 K7.O2
N$31
  Bottom 0.813: K8.P2 27.94,27.14 C40.2 28.02,26.51 C44.1
N$32
  Bottom 0.813: K9.O1 25.39,11.27 20.95,15.71 11.42,15.71 11.42,21.43 C46.2
N$33
  Bottom 0.813: C47.2 28.57,14.44 30.48,12.54 30.55,9.44 25.39,4.28 K9.O2
N$34
  Bottom 0.406: IC2.2 93.34,33.49 RN1.3 95.88,30.32 93.34,27.78 IC1.9
N$35
  Bottom 0.813: 52.06,32.86 C41.1 | C41.1 49.52,40.48 | C41.1 50.24,32.86 52.06,32.86 | 52.06,32.86 52.7,32.86 C53.1 54.6,27.9 L13.1 | 49.52,40.48 C55.1 | 49.52,40.48 C41.3
N$36
  Bottom 0.813: 58.41,6.82 C43.1 48.25,6.82 | C54.2 72.39,18.25 60.95,18.25 60.95,18.38 L14.1 58.92,16.35 C56.2 52.7,15.71 48.25,11.27 48.25,6.82 | C43.3 48.25,6.82
N$37
  Bottom 0.813: C43.2 55.79,10 C49.1 70.48,10 C54.1 76.2,18.25 76.2,30.32 68.58,30.32 K10.P2
N$38
  Bottom 0.813: C56.1 48.89,18.89 | 63.49,25.87 56.51,25.87 53.34,22.7 48.89,22.7 | 48.89,18.89 48.89,22.7 | 48.89,18.89 48.89,20.16 | 48.89,22.7 48.89,20.16 | 48.89,22.7 48.89,29.05 | 48.89,29.05 C50.1 | 48.89,20.16 L15.1 | 48.89,29.05 C55.2 | 63.49,25.87 C52.1 | 63.49,25.87 C52.3
N$39
  Bottom 0.406: IC2.3 92.07,32.22 RN1.4 93.34,29.68 92.07,28.41 IC1.8
N$40
  Bottom 0.406: IC1.7 RN1.5 IC2.4
N$41
  Bottom 0.406: IC2.5 89.53,32.22 RN1.6 88.26,29.68 89.53,28.41 IC1.6
N$42
  Bottom 0.406: IC2.6 88.26,33.49 RN1.7 85.72,30.32 88.26,27.78 IC1.5
N$43
  Bottom 0.406: IC2.7 86.99,34.12 86.36,33.49 85.09,33.49 83.18,31.59 RN1.8 86.99,27.14 IC1.4
N$44
  Bottom 0.406: IC1.11 95.88,23.96 99.06,20.79 99.06,16.98 RN2.8 103.5,2.38 IC3.7
N$45
  Bottom 0.406: IC1.13 100.96,13.02 RN2.7 100.96,3.65 IC3.6
N$46
  Bottom 0.406: IC1.14 95.88,15.08 96.52,14.44 97.79,14.44 98.42,13.81 RN2.6 98.42,4.92 IC3.5
N$47
  Bottom 0.406: IC1.15 94.61,13.81 RN2.5 95.88,6.18 IC3.4
N$48
  Bottom 0.406: IC1.16 RN2.4 94.61,11.27 94.61,7.46 IC3.3
N$49
  Bottom 0.406: 92.07,16.98 IC1.17 92.07,15.08 90.8,13.81 RN2.3 93.34,10 93.34,8.73 IC3.2
N$50
  Bottom 0.406: IC1.18 90.8,15.71 88.26,13.17 RN2.2 88.26,11.9 89.53,10.63 89.53,10 IC3.1
N$51  (via drill 0.7 pad 1.02)
  Top 0.61: K1.10 1.27,48.09 1.27,8.09 5.71,3.65 13.96,3.65 15.23,4.92 31.75,4.92 34.92,1.74 75.56,1.74 75.56,32.22 81.91,38.57 v81.91,41.74
  Bottom 0.61: v81.91,41.74 81.91,43.65 86.99,43.65 IC2.10
N$52
  Bottom 0.813: K11.O2 K11.O1
N$53
  Top 0.406: R2.2 128.9,33.49
  Top 0.61: 126.36,33.81 126.36,27.14 K11.S1
  Top 0.813: 128.9,33.49 R1.1 | 126.36,33.81 R2.2
N$54  (via drill 0.7, 0.7 pad 1.02)
  Top 0.61: v67.94,44.92 45.08,44.92 v45.08,53.18 | v34.92,57.62 34.92,77.94 41.27,84.29 K2.10
  Bottom 0.61: IC2.11 88.26,44.92 v67.94,44.92 | v45.08,53.18 39.36,53.18 v34.92,57.62
N$55  (via drill 0.7 pad 1.02)
  Top 0.61: v37.46,43.02 v37.46,51.27 | v77.47,4.28 77.47,31.59 85.09,39.2 v89.53,39.2
  Bottom 0.61: v37.46,43.02 37.46,37.3 41.9,32.86 41.9,10 47.62,4.28 v77.47,4.28 | 89.53,39.84 IC2.12 v89.53,39.2 | K3.10 49.52,54.45 46.35,51.27 v37.46,51.27
N$56  (via drill 0.7, 0.7 pad 1.02)
  Top 0.406: v74.93,46.19 v74.93,49.37
  Bottom 0.61: IC2.13 90.8,46.19 v74.93,46.19 | K4.10 78.73,57.62 76.83,57.62 76.83,51.27 v74.93,49.37
N$57  (via drill 0.7, 0.7 pad 1.02)
  Top 0.406: K5.10 65.4,78.57 69.21,78.57 72.39,75.4 80.64,75.4 83.18,72.86 93.98,72.86 93.98,58.26 v99.69,52.54 | v92.07,46.19 93.98,47.46 v93.98,49.37
  Bottom 0.406: v99.69,52.54 99.69,49.37 v93.98,49.37 | IC2.14 v92.07,46.19
N$58  (via drill 0.7 pad 1.02)
  Top 0.61: v106.04,45.55 v109.85,50
  Bottom 0.61: IC2.15 93.34,45.55 v106.04,45.55 | v109.85,50 109.85,53.18 K6.10
N$59  (via drill 0.7 pad 1.02)
  Top 0.61: v147.95,72.22 139.69,80.48 139.69,88.1 137.16,90.64 123.82,90.64 K7.10
  Bottom 0.61: IC2.16 94.61,39.2 122.55,39.2 132.71,49.37 137.79,49.37 143.5,55.08 143.5,60.8 147.95,65.24 v147.95,72.22
N$60  (via drill 0.7)
  Top 0.61: v40.63,3.65 37.46,3.65 37.46,30.95 K8.10
  Bottom 0.406: IC3.10 81.91,2.38 80.64,1.1
  Bottom 0.61: v40.63,3.65 43.17,1.1 80.64,1.1
N$61
  Bottom 0.406: IC3.11 81.28,3.65 80.01,2.38
  Bottom 0.61: 80.01,2.38 45.08,2.38 41.9,5.55 38.73,5.55 35.55,2.38 K9.10
N$62
  Bottom 0.406: 81.28,4.92 IC3.12
  Bottom 0.61: 81.28,4.92 78.73,7.46 78.73,32.86 K10.10
N$63
  Top 0.813: 123.82,33.49 R1.2 | K11.S2 123.82,27.14 123.82,33.49 | R3.1 121.28,33.49 123.82,33.49
N$64
  Bottom 0.813: K12.P1 K11.P2
N$65
  Top 0.813: K12.O2 K12.O1
N$66
  Top 0.61: 113.66,33.49 113.66,27.14 K12.S1
  Top 0.813: R5.2 116.2,33.49 113.66,33.49 R4.1
N$67
  Top 0.406: 111.12,33.49 R4.2
  Top 0.813: K12.S2 111.12,27.14 111.12,33.49 | R4.2 108.58,33.49 R6.1
N$68  (via drill 0.7)
  Top 0.406: v82.55,6.18 85.09,6.18 85.72,5.55 v107.31,5.55
  Bottom 0.406: v82.55,6.18 IC3.13
  Bottom 0.61: v107.31,5.55 K11.10
N$69  (via drill 0.7)
  Top 0.406: v82.55,8.09 85.09,8.09 86.36,6.82 102.87,6.82 v108.58,12.54
  Bottom 0.406: v82.55,8.09 83.18,7.46 IC3.14
  Bottom 0.61: v108.58,12.54 K12.10
N$70  (via drill 0.7)
  Top 0.61: X3.1 147.31,17.62 130.81,1.1 79.37,1.1 79.37,19.52 v85.72,19.52
  Bottom 0.61: v85.72,19.52 IC1.22
N$71  (via drill 0.7)
  Top 0.61: X3.2 147.31,20.16 129.53,2.38 81.28,2.38 v81.28,11.27
  Bottom 0.406: IC1.23 84.45,16.98
  Bottom 0.61: v81.28,11.27 81.28,11.9 84.45,15.08 IC1.23
N$72
  Top 0.61: R7.1 LED1.C
N$73
  Top 0.61: EMI1.1 153.03,28.41 X3.5
N$74
  Top 0.61: EMI2.1 X3.4
N$76
  Top 0.813: K11.P1 129.53,24.6 139.38,34.44 | 139.38,34.44 145.41,40.48 X1.1 | D1.C | 139.38,34.44 D1.C
RF_IN_ATT  (via drill 0.7)
  Top 0.61: K12.P2 104.77,24.6 v104.77,41.11
  Bottom 0.61: 110.48,47.46 v104.77,41.11
  Bottom 0.813: K1.S1 20.32,47.46 25.39,47.46 | 25.39,47.46 57.78,47.46 | 57.78,47.46 66.04,47.46 | 66.04,47.46 86.99,47.46 | 86.99,47.46 110.48,47.46 110.48,46.19 121.28,46.19 K6.S1 | 25.39,47.46 K8.S1 | 57.78,47.46 K3.S1 | 66.04,47.46 K10.S1 | 86.99,47.46 K4.S1
RF_OUT
  Top 0.813: 121.28,54.45 138.43,54.45 140.97,56.98 X2.1 | 121.28,54.45 K6.S2 | 121.28,54.45 120.65,53.81 110.48,53.81 107.31,50.63 96.52,50.63 92.7,54.45 86.99,54.45 | 86.99,54.45 K4.S2 | 86.99,54.45 76.83,54.45 76.83,51.27 | 76.83,51.27 64.77,51.27 61.59,54.45 57.78,54.45 | 57.78,54.45 K3.S2 | 40,54.45 57.78,54.45 | 40,54.45 23.49,54.45 K1.S2 | K10.S2 66.04,33.49 69.21,36.66 76.83,36.66 76.83,51.27 | K8.S2 25.39,39.2 40,39.2 40,54.45

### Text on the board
Top: Bandpassfilter 160m - 6m | TOP | RF_out | RF_in | www.Marcus-Pool.de | DG9BFJ | 03/12 | Rev 2.1
Bottom: BOTTOM
tPlace: Att 20dB | Att 10dB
